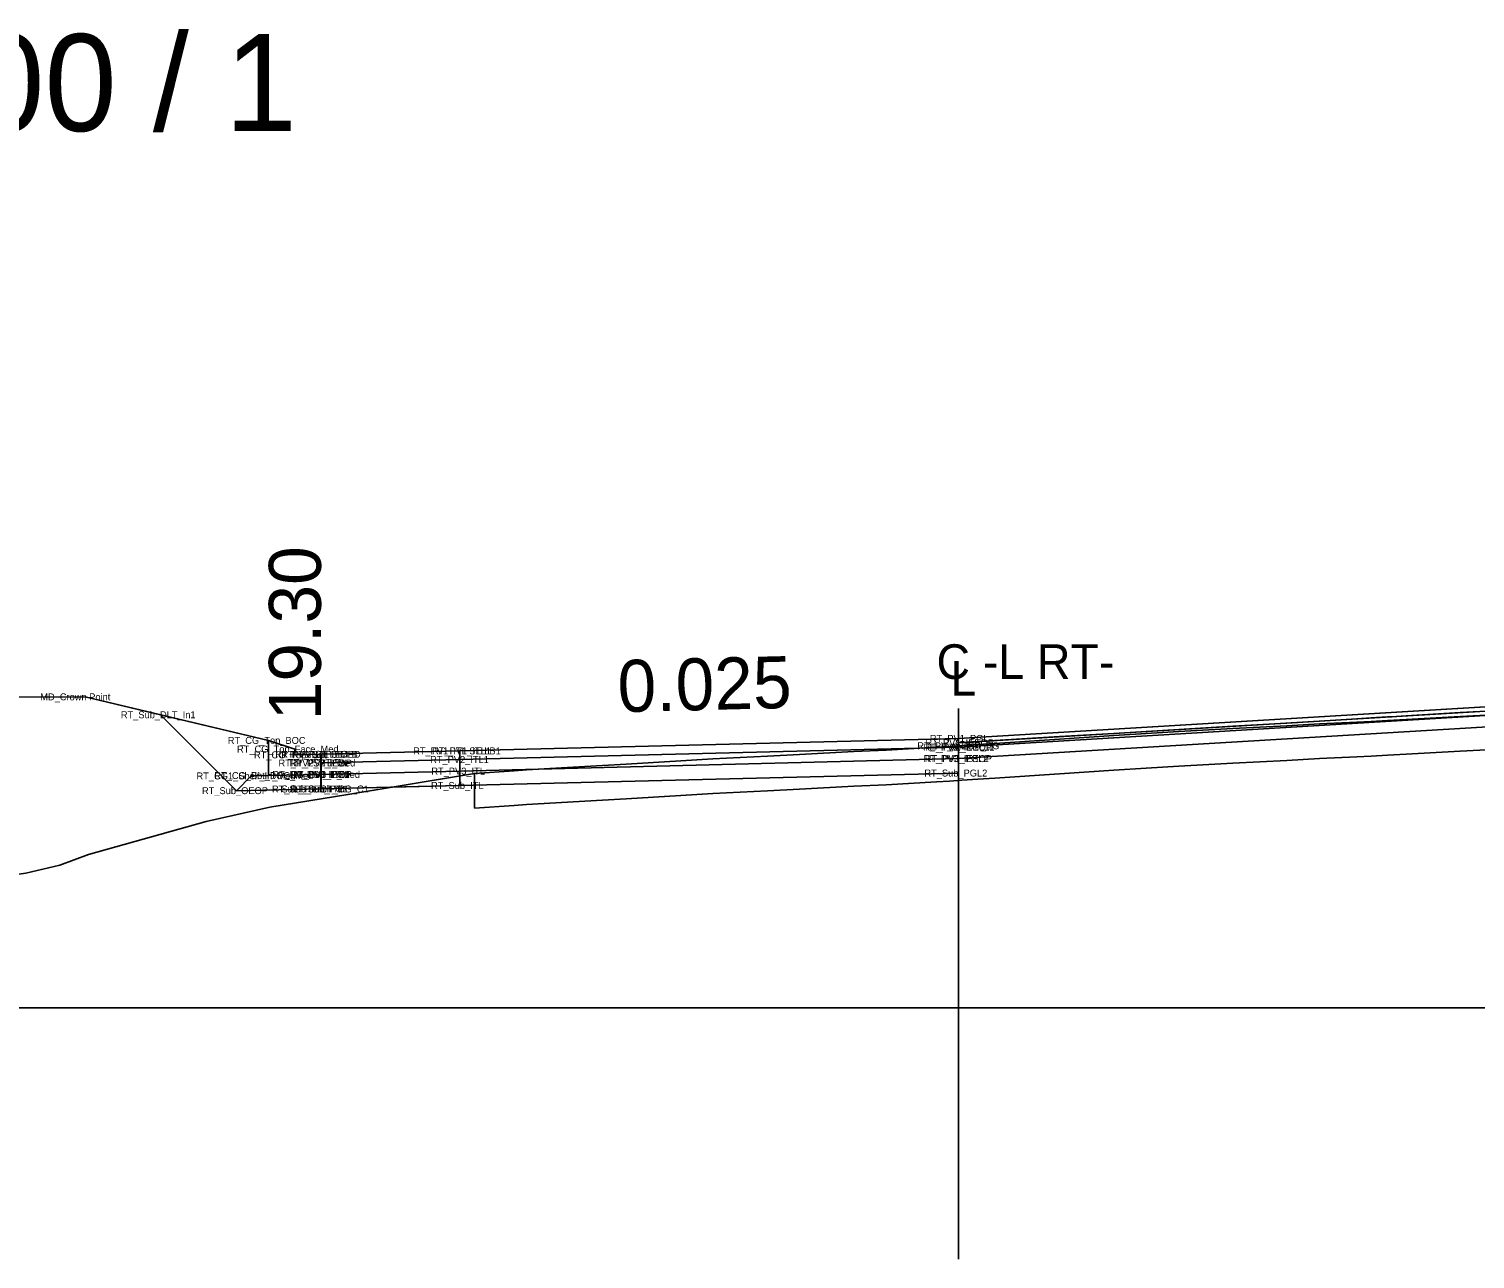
# Model space of a CAD drawing. Extents: x 2177029 to 2201446, y 59897 to 78390.
# Drawn here: x 2199245.92 to 2199287.63, y 68400.06 to 68435.56 of the extents above; entities that cross this region are included whole.
import ezdxf

# ---------------------------------------------------------------- set-up
doc = ezdxf.new("R2010")
doc.units = 0
for name, color, linetype in [('Exist CMT Pavement', 7, 'Continuous'), ('Exist Cross Section Cell', 7, 'Continuous'), ('Exist PHM Roadway Shape', 7, 'Continuous'), ('Exist XS Ground Line', 7, 'Continuous'), ('Old_Level_11', 7, 'Continuous'), ('Prop CMT Conc Surface', 7, 'Continuous'), ('Prop CMT Concrete Structures', 7, 'Continuous'), ('Prop CMT Guardrail Graphics', 7, 'Continuous'), ('Prop CMT Pvmt Course 1 CG', 7, 'Continuous'), ('Prop CMT Pvmt Course 2', 7, 'Continuous'), ('Prop CMT Pvmt Course 2 CG', 7, 'Continuous'), ('Prop CMT Pvmt Course 3', 7, 'Continuous'), ('Prop CMT Pvmt Course 4', 7, 'Continuous'), ('Prop CMT Pvmt Surface', 7, 'Continuous'), ('Prop CMT Pvmt Wedge Surface 1', 7, 'Continuous'), ('Prop CMT Slope Grass', 7, 'Continuous'), ('Prop CMT Subgrade Earthwork', 7, 'Continuous'), ('Prop CMT Top Wall Envelope', 7, 'Continuous'), ('Prop Hatching', 7, 'Continuous'), ('Prop Horizontal Alignment', 7, 'Continuous'), ('Prop Retaining Wall', 7, 'Continuous'), ('Prop Terminator CELL', 7, 'Continuous'), ('Prop XS Side Slope Text', 7, 'Continuous'), ('Scratch_Level_0', 7, 'Continuous'), ('Scratch_Level_9', 7, 'Continuous')]:
    doc.layers.add(name, color=color, linetype=linetype)

msp = doc.modelspace()

# ---------------------------------------------------------------- linework, layer by layer
at = {"layer": 'Exist CMT Pavement'}
msp.add_line((2199272.732, 68400.057), (2199272.732, 68415.951), dxfattribs=at)
at = {"layer": 'Exist Cross Section Cell'}
msp.add_line((2199242.732, 68407.31), (2199442.732, 68407.31), dxfattribs=at)
at = {"layer": 'Exist XS Ground Line'}
msp.add_lwpolyline([(2199245.829, 68411.194), (2199246.809, 68411.425), (2199247.642, 68411.738), (2199251.038, 68412.688), (2199252.873, 68413.103), (2199255.123, 68413.462), (2199258.769, 68414.071), (2199259.919, 68414.15), (2199260.276, 68414.18), (2199262.461, 68414.304), (2199263.149, 68414.341), (2199264.722, 68414.436), (2199265.649, 68414.491), (2199267.219, 68414.573), (2199268.148, 68414.62), (2199269.717, 68414.701), (2199270.648, 68414.747), (2199272.099, 68414.832), (2199272.473, 68414.854), (2199272.832, 68414.876), (2199273.294, 68414.906), (2199273.781, 68414.939), (2199275.648, 68415.061), (2199277.211, 68415.165), (2199278.148, 68415.228), (2199279.088, 68415.279), (2199280.649, 68415.365), (2199282.207, 68415.45), (2199283.149, 68415.502), (2199284.218, 68415.554), (2199284.633, 68415.573), (2199285.107, 68415.596), (2199285.649, 68415.628), (2199287.202, 68415.715), (2199288.148, 68415.768)], dxfattribs=at)
at = {"layer": 'Prop CMT Conc Surface'}
for points in [[(2199272.732, 68414.959), (2199308.733, 68417.119)], [(2199272.732, 68415.084), (2199272.732, 68414.834), (2199272.732, 68414.834), (2199272.732, 68414.959)]]:
    msp.add_lwpolyline(points, dxfattribs=at)
at = {"layer": 'Prop CMT Concrete Structures'}
for p, q in [((2199272.732, 68415.084), (2199308.733, 68417.244)), ((2199272.732, 68415.084), (2199258.354, 68414.724)), ((2199254.343, 68414.624), (2199254.342, 68414.624)), ((2199254.352, 68414.624), (2199254.343, 68414.624)), ((2199258.354, 68414.724), (2199258.352, 68414.724))]:
    msp.add_line(p, q, dxfattribs=at)
at = {"layer": 'Prop CMT Guardrail Graphics'}
for points in [[(2199272.732, 68414.5), (2199308.733, 68416.66)], [(2199272.732, 68415.084), (2199272.732, 68414.5)]]:
    msp.add_lwpolyline(points, dxfattribs=at)
at = {"layer": 'Prop CMT Pvmt Course 1 CG'}
for points in [[(2199254.352, 68414.041), (2199258.352, 68414.141)], [(2199254.352, 68413.624), (2199254.352, 68414.041)], [(2199258.352, 68414.141), (2199258.352, 68413.724)], [(2199258.352, 68413.724), (2199254.352, 68413.624)]]:
    msp.add_lwpolyline(points, dxfattribs=at)
at = {"layer": 'Prop CMT Pvmt Course 2'}
for points in [[(2199272.732, 68414.5), (2199258.352, 68414.141)], [(2199272.732, 68414.084), (2199272.732, 68414.5)], [(2199254.352, 68414.041), (2199254.342, 68414.041)], [(2199254.342, 68414.041), (2199254.342, 68413.624)], [(2199254.352, 68413.624), (2199254.352, 68414.041)], [(2199258.352, 68414.141), (2199258.352, 68413.724)], [(2199258.352, 68413.724), (2199272.732, 68414.084)], [(2199254.342, 68413.624), (2199254.352, 68413.624)]]:
    msp.add_lwpolyline(points, dxfattribs=at)
at = {"layer": 'Prop CMT Pvmt Course 2 CG'}
for points in [[(2199272.732, 68415.084), (2199308.733, 68417.244)], [(2199308.733, 68417.119), (2199272.732, 68414.959)], [(2199272.732, 68415.084), (2199258.352, 68414.724)], [(2199272.732, 68414.834), (2199272.732, 68415.084)], [(2199272.732, 68414.834), (2199272.732, 68415.084)], [(2199254.352, 68414.624), (2199254.342, 68414.624)], [(2199254.342, 68414.624), (2199254.342, 68414.374)], [(2199254.352, 68414.374), (2199254.352, 68414.624)], [(2199258.352, 68414.474), (2199272.732, 68414.834)], [(2199258.352, 68414.724), (2199258.352, 68414.474)], [(2199272.732, 68414.959), (2199272.732, 68414.834), (2199272.732, 68414.834)], [(2199254.342, 68414.374), (2199254.352, 68414.374)]]:
    msp.add_lwpolyline(points, dxfattribs=at)
at = {"layer": 'Prop CMT Pvmt Course 3'}
msp.add_line((2199272.732, 68414.87), (2199272.732, 68414.084), dxfattribs=at)
for points in [[(2199249.716, 68415.766), (2199251.907, 68413.575)], [(2199258.352, 68413.724), (2199272.732, 68414.084)], [(2199254.342, 68413.624), (2199251.907, 68413.575)], [(2199254.352, 68413.624), (2199254.342, 68413.624)], [(2199254.342, 68413.624), (2199254.342, 68413.624)], [(2199258.352, 68413.724), (2199254.352, 68413.624)]]:
    msp.add_lwpolyline(points, dxfattribs=at)
at = {"layer": 'Prop CMT Pvmt Course 4'}
msp.add_lwpolyline([(2199258.352, 68414.724), (2199254.352, 68414.624)], dxfattribs=at)
at = {"layer": 'Prop CMT Pvmt Surface'}
for points in [[(2199272.732, 68414.959), (2199272.832, 68414.965), (2199273.294, 68414.993), (2199273.781, 68415.022), (2199275.648, 68415.134), (2199277.211, 68415.228), (2199278.148, 68415.284), (2199279.088, 68415.341), (2199280.649, 68415.434), (2199282.207, 68415.528), (2199283.149, 68415.584), (2199284.218, 68415.649), (2199284.633, 68415.673), (2199285.107, 68415.702), (2199285.239, 68415.71), (2199285.356, 68415.717), (2199285.649, 68415.734), (2199287.202, 68415.828), (2199288.148, 68415.884)], [(2199288.148, 68415.768), (2199287.202, 68415.715), (2199285.649, 68415.628), (2199285.356, 68415.611), (2199285.239, 68415.605), (2199285.107, 68415.596), (2199284.633, 68415.573), (2199284.218, 68415.554), (2199283.149, 68415.502), (2199282.207, 68415.45), (2199280.649, 68415.365), (2199279.088, 68415.279), (2199278.148, 68415.228), (2199277.211, 68415.165), (2199275.648, 68415.061), (2199273.781, 68414.939), (2199273.294, 68414.906), (2199272.832, 68414.876), (2199272.732, 68414.87)], [(2199272.732, 68414.87), (2199272.732, 68414.959)]]:
    msp.add_lwpolyline(points, dxfattribs=at)
at = {"layer": 'Prop CMT Pvmt Wedge Surface 1'}
for p, q in [((2199284.218, 68414.554), (2199284.633, 68414.573)), ((2199284.633, 68414.573), (2199285.107, 68414.596)), ((2199285.107, 68414.596), (2199285.649, 68414.628)), ((2199285.649, 68414.628), (2199287.202, 68414.715)), ((2199287.202, 68414.715), (2199288.148, 68414.768)), ((2199275.648, 68414.061), (2199277.211, 68414.165)), ((2199277.211, 68414.165), (2199278.148, 68414.228)), ((2199278.148, 68414.228), (2199279.088, 68414.279)), ((2199279.088, 68414.279), (2199280.649, 68414.365)), ((2199280.649, 68414.365), (2199282.207, 68414.45)), ((2199282.207, 68414.45), (2199283.149, 68414.502)), ((2199283.149, 68414.502), (2199284.218, 68414.554)), ((2199258.769, 68413.071), (2199258.769, 68414.071)), ((2199269.717, 68413.701), (2199270.648, 68413.747)), ((2199270.648, 68413.747), (2199272.099, 68413.832)), ((2199272.099, 68413.832), (2199272.473, 68413.854)), ((2199272.473, 68413.854), (2199272.832, 68413.876)), ((2199272.832, 68413.876), (2199273.294, 68413.906)), ((2199273.294, 68413.906), (2199273.781, 68413.939)), ((2199273.781, 68413.939), (2199275.648, 68414.061)), ((2199262.461, 68413.304), (2199263.149, 68413.341)), ((2199263.149, 68413.341), (2199264.722, 68413.436)), ((2199264.722, 68413.436), (2199265.649, 68413.491)), ((2199265.649, 68413.491), (2199267.219, 68413.573)), ((2199267.219, 68413.573), (2199268.148, 68413.62)), ((2199268.148, 68413.62), (2199269.717, 68413.701)), ((2199258.769, 68413.071), (2199259.919, 68413.15)), ((2199259.919, 68413.15), (2199260.276, 68413.18)), ((2199260.276, 68413.18), (2199262.461, 68413.304))]:
    msp.add_line(p, q, dxfattribs=at)
at = {"layer": 'Prop CMT Slope Grass'}
for points in [[(2199272.732, 68414.834), (2199258.352, 68414.474)], [(2199272.732, 68414.5), (2199272.732, 68414.834)], [(2199254.352, 68414.374), (2199254.342, 68414.374)], [(2199254.342, 68414.374), (2199254.342, 68414.041)], [(2199254.352, 68414.041), (2199254.352, 68414.374)], [(2199258.352, 68414.141), (2199272.732, 68414.5)], [(2199258.352, 68414.474), (2199258.352, 68414.141)], [(2199254.342, 68414.041), (2199254.352, 68414.041)]]:
    msp.add_lwpolyline(points, dxfattribs=at)
at = {"layer": 'Prop CMT Subgrade Earthwork'}
for points in [[(2199272.732, 68414.834), (2199308.733, 68416.994)], [(2199272.732, 68415.084), (2199272.732, 68414.834)]]:
    msp.add_lwpolyline(points, dxfattribs=at)
at = {"layer": 'Prop Hatching'}
for points in [[(2199242.252, 68416.273), (2199247.541, 68416.283)], [(2199252.832, 68415.026), (2199247.541, 68416.283)]]:
    msp.add_lwpolyline(points, dxfattribs=at)
at = {"layer": 'Prop Horizontal Alignment'}
for points in [[(2199254.342, 68414.041), (2199252.331, 68414), (2199251.907, 68413.575)], [(2199254.342, 68413.624), (2199254.342, 68414.041)], [(2199251.907, 68413.575), (2199254.342, 68413.624)]]:
    msp.add_lwpolyline(points, dxfattribs=at)
at = {"layer": 'Prop Retaining Wall'}
msp.add_lwpolyline([(2199254.342, 68414.624), (2199253.592, 68414.609), (2199253.591, 68414.776), (2199252.832, 68415.026)], dxfattribs=at)
at = {"layer": 'Prop Terminator CELL'}
for points in [[(2199254.342, 68414.624), (2199253.592, 68414.609), (2199253.591, 68414.776), (2199252.832, 68415.026)], [(2199252.832, 68415.026), (2199252.832, 68414.01)], [(2199254.342, 68414.041), (2199254.342, 68414.624)], [(2199252.832, 68414.01), (2199254.342, 68414.041)]]:
    msp.add_lwpolyline(points, dxfattribs=at)
at = {"layer": 'Prop XS Side Slope Text'}
msp.add_lwpolyline([(2199308.742, 68417.244), (2199272.732, 68415.084), (2199258.352, 68414.724), (2199254.352, 68414.624), (2199253.592, 68414.609), (2199253.591, 68414.776), (2199252.832, 68415.026), (2199249.715, 68415.767), (2199251.907, 68413.575), (2199254.352, 68413.624), (2199256.402, 68413.676), (2199258.769, 68414.071), (2199259.919, 68414.15), (2199260.276, 68414.18), (2199262.461, 68414.304), (2199263.149, 68414.341), (2199264.722, 68414.436), (2199265.649, 68414.491), (2199267.219, 68414.573), (2199268.148, 68414.62), (2199269.717, 68414.701), (2199270.648, 68414.747), (2199272.099, 68414.832), (2199272.473, 68414.854), (2199272.732, 68414.87), (2199272.832, 68414.876), (2199273.294, 68414.906), (2199273.781, 68414.939), (2199275.648, 68415.061), (2199277.211, 68415.165), (2199278.148, 68415.228), (2199279.088, 68415.279), (2199280.649, 68415.365), (2199282.207, 68415.45), (2199283.149, 68415.502), (2199284.218, 68415.554), (2199284.633, 68415.573), (2199285.107, 68415.596), (2199285.649, 68415.628), (2199287.202, 68415.715), (2199288.148, 68415.768)], dxfattribs=at)
for points in [[(2199243.722, 68410.904), (2199244.796, 68411.051), (2199245.829, 68411.194), (2199246.809, 68411.425), (2199247.642, 68411.738), (2199251.038, 68412.688), (2199252.873, 68413.103), (2199255.123, 68413.462), (2199256.402, 68413.676), (2199254.352, 68413.624), (2199251.907, 68413.575), (2199249.715, 68415.767), (2199247.541, 68416.283), (2199244.538, 68416.278), (2199243.159, 68414.898), (2199242.732, 68414.888), (2199242.732, 68411.039)], [(2199272.732, 68414.87), (2199272.732, 68414.084), (2199258.352, 68413.724), (2199256.402, 68413.676), (2199258.769, 68414.071), (2199259.919, 68414.15), (2199260.276, 68414.18), (2199262.461, 68414.304), (2199263.149, 68414.341), (2199264.722, 68414.436), (2199265.649, 68414.491), (2199267.219, 68414.573), (2199268.148, 68414.62), (2199269.717, 68414.701), (2199270.648, 68414.747), (2199272.099, 68414.832), (2199272.473, 68414.854)]]:
    msp.add_lwpolyline(points, close=True, dxfattribs=at)
at = {"layer": 'Scratch_Level_0'}
for points in [[(2199258.352, 68414.474), (2199254.352, 68414.374)], [(2199254.352, 68414.374), (2199254.352, 68414.041)], [(2199258.352, 68414.141), (2199258.352, 68414.474)], [(2199254.352, 68414.041), (2199258.352, 68414.141)]]:
    msp.add_lwpolyline(points, dxfattribs=at)
at = {"layer": 'Scratch_Level_9'}
for points in [[(2199258.352, 68414.724), (2199254.352, 68414.624)], [(2199254.352, 68414.624), (2199254.352, 68414.374)], [(2199258.352, 68414.474), (2199258.352, 68414.724)], [(2199254.352, 68414.374), (2199258.352, 68414.474)]]:
    msp.add_lwpolyline(points, dxfattribs=at)

# ---------------------------------------------------------------- texts
at = {"layer": 'Exist CMT Pavement'}
for s, p in [('C -L RT-', (2199272.099, 68416.799)), ('L', (2199272.501, 68416.318))]:
    msp.add_text(s, height=1, dxfattribs=at).set_placement(p)
at = {"layer": 'Exist Cross Section Cell'}
msp.add_text('37+50.00 / 1', height=2.8, dxfattribs=at).set_placement((2199232.732, 68432.609))
at = {"layer": 'Exist PHM Roadway Shape'}
for s, p in [('MD_Crown Point', (2199246.248, 68416.183)), ('RT_Sub_DLT_In1', (2199248.573, 68415.666)), ('RT_CG_Top_BOC', (2199251.656, 68414.926)), ('RT_PV1_IEEOP', (2199271.779, 68414.859)), ('RT_PV1_PGL', (2199271.905, 68414.984)), ('RT_CG_Top_Face_Med', (2199251.923, 68414.676)), ('RT_CG_Top_Gut', (2199252.411, 68414.509)), ('RT_PV1_ITL SE LB', (2199253.027, 68414.524)), ('RT_PV1_ITL_MED', (2199253.2, 68414.524)), ('RT_PS1_IEOP', (2199253.492, 68414.524)), ('RT_PV1_ITL SE LB1', (2199257.004, 68414.624)), ('RT_PV2_ITL1', (2199257.494, 68414.374)), ('RT_PV1_ITL1', (2199257.551, 68414.624)), ('RT_PV_IEEOP_EG', (2199271.546, 68414.77)), ('RT_PV2_IEEOP', (2199271.722, 68414.734)), ('RT_PV3_IEEOP', (2199271.722, 68414.4)), ('RT_PV3_PGL2', (2199271.759, 68414.4)), ('RT_PV2_PGL11', (2199271.782, 68414.734)), ('RT_PV2_ITL_med', (2199253.12, 68414.274)), ('RT_PS2_IEOP', (2199253.435, 68414.274)), ('RT_PV2_PGL', (2199253.468, 68414.274)), ('RT_PV3_ITL', (2199257.527, 68414.041)), ('RT_Sub_PGL2', (2199271.749, 68413.984)), ('RT_CG1_Shelf_In_Med', (2199250.755, 68413.9)), ('RT_CG_Bot_BOC_Med', (2199251.27, 68413.91)), ('RT_CG_Bot_IE_Med', (2199252.943, 68413.941)), ('RT_PS3_IEOP', (2199253.435, 68413.941)), ('RT_PV3_PGL', (2199253.468, 68413.941)), ('RT_PV3_ITL1', (2199253.484, 68413.941)), ('RT_Sub_ITL', (2199257.518, 68413.624)), ('RT_Sub_OEOP', (2199250.913, 68413.475)), ('RT_Sub_IEOT_CG_C1', (2199252.929, 68413.524)), ('Sub_Trench_In', (2199253.204, 68413.524)), ('RT_Sub_PGL', (2199253.459, 68413.524)), ('RT_Sub_ITL1', (2199253.474, 68413.524))]:
    msp.add_text(s, height=0.2, dxfattribs=at).set_placement(p)
at = {"layer": 'Old_Level_11'}
msp.add_text('0.025', height=1.5, rotation=1.4341, dxfattribs=at).set_placement((2199262.917, 68415.839))
at = {"layer": 'Prop CMT Top Wall Envelope'}
msp.add_text('19.30', height=1.5, rotation=90, dxfattribs=at).set_placement((2199254.342, 68415.609))

doc.saveas('drawing.dxf')
